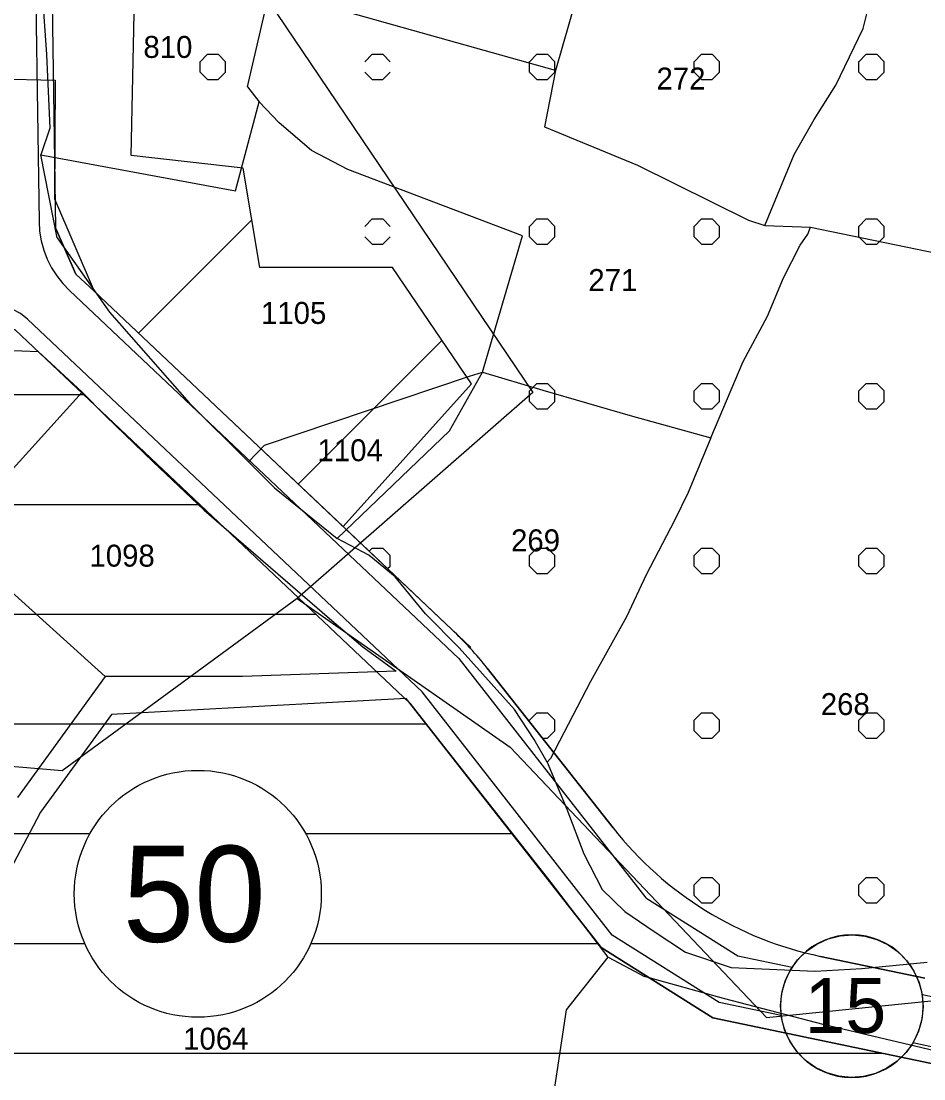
# Model space of a CAD drawing. Extents: x 410727 to 412947, y 4463506 to 4466382.
# Drawn here: x 411199.7 to 411364.1, y 4465992.7 to 4466185.4 of the extents above; entities that cross this region are included whole.
import ezdxf

# ---------------------------------------------------------------- set-up
doc = ezdxf.new("R2010")
doc.units = 0
for name, color, linetype in [('ADAKENARI', 7, 'Continuous'), ('KALDIRIM', 7, 'Continuous'), ('KDS_PARSEL_NO', 7, 'Continuous'), ('KDS_PL', 7, 'Continuous'), ('PL_KA_TARIM_OZEL', 7, 'Continuous'), ('PL_KON_ONE_50', 7, 'Continuous'), ('sembol', 7, 'Continuous'), ('SM_BEYAZ', 7, 'Continuous'), ('SM_DAİRE', 7, 'Continuous'), ('SM_YOLGEN', 7, 'Continuous'), ('SNR_KOYLER', 7, 'Continuous'), ('SNR_TR_AZGELISME', 7, 'Continuous'), ('TR_GELİŞME_KONUT_ÇOKAZ', 7, 'Continuous'), ('TR_OZELMAHSUL', 7, 'Continuous'), ('Yerlesime_uygunluk_sınırı', 7, 'Continuous')]:
    doc.layers.add(name, color=color, linetype=linetype)

msp = doc.modelspace()

# ---------------------------------------------------------------- linework, layer by layer
at = {"layer": 'ADAKENARI'}
for p, q in [((411205.32, 4466188.73), (411205.95, 4466147.79)), ((411209.66, 4466139.36), (411205.95, 4466147.79)), ((411212.98, 4466136.22), (411209.66, 4466139.36)), ((411258.32, 4466093.35), (411212.98, 4466136.22)), ((411281.62, 4466071.32), (411241.81, 4466108.96)), ((411278.17, 4466074.59), (411258.32, 4466093.35)), ((411307.51, 4466038.45), (411284.58, 4466067.56)), ((411364.32, 4466011.06), (411345.29, 4466015.03))]:
    msp.add_line(p, q, dxfattribs=at)
msp.add_lwpolyline([(411117.76, 4466023.84), (411156.49, 4466097.39), (411191.27, 4466129.24), (411198.59, 4466129.18), (411270.5, 4466061.2), (411305.33, 4466016.64), (411325.67, 4466003.81), (411366.7, 4465995.24)], dxfattribs=at)
for centre, start, end in [((411233.51, 4466027.35), 38.2144, 46.6065), ((411233.51, 4466027.35), 38.2144, 46.6065), ((411358.58, 4466078.66), 218.2144, 258.2027), ((411358.58, 4466078.66), 218.2144, 258.2027)]:
    msp.add_arc(centre, 65, start, end, dxfattribs=at)
at = {"layer": 'KALDIRIM'}
for points in [[(411198.93, 4466275.12), (411202.14, 4466255.53), (411208.26, 4466254.88), (411203.85, 4466225), (411202.32, 4466188.77), (411202.93, 4466148.93), (411203.04, 4466147.17), (411203.33, 4466145.44), (411203.79, 4466143.74), (411204.42, 4466142.09), (411205.21, 4466140.52), (411206.15, 4466139.03), (411207.24, 4466137.64), (411208.46, 4466136.37), (411279.4, 4466069.3), (411313.49, 4466025.68), (411330.24, 4466015.11), (411340.12, 4466013.05)], [(411338.13, 4466004.27), (411326.82, 4466006.63), (411307.37, 4466018.9), (411272.72, 4466063.22), (411200.86, 4466131.17), (411199.58, 4466132.17), (411198.14, 4466132.91), (411196.58, 4466133.37), (411194.96, 4466133.54), (411193.34, 4466133.4), (411191.78, 4466132.96), (411190.32, 4466132.24), (411189.03, 4466131.26), (411146.18, 4466092.01), (411131.2, 4466084.63), (411083.45, 4466076.24), (411040.64, 4466082.04), (411015.99, 4466078.54), (410988.76, 4466066.47)], [(411363.84, 4466008.09), (411368.56, 4466007.11), (411402.12, 4466003.58), (411420.29, 4465997.93), (411448.26, 4465982.75), (411504.51, 4465923.06), (411515.54, 4465913.29), (411544.92, 4465897.92), (411576.35, 4465881.49), (411596.27, 4465871.64)], [(411400.3, 4465994.72), (411367.17, 4465998.21), (411362.15, 4465999.25)]]:
    msp.add_lwpolyline(points, dxfattribs=at)
at = {"layer": 'KDS_PL'}
for p, q in [((411305.07, 4466204.22), (411297.02, 4466176.47)), ((411203.54, 4466190.27), (411204.27, 4466179.37)), ((411297.02, 4466176.47), (411245.89, 4466190.84)), ((411240.94, 4466173.48), (411244.24, 4466187.9)), ((411353.1, 4466184.12), (411353.76, 4466186.78)), ((411348.12, 4466173.81), (411353.1, 4466184.12)), ((411204.27, 4466179.37), (411204.89, 4466165.95)), ((411297.02, 4466176.47), (411295.03, 4466166.17)), ((411240.94, 4466173.48), (411243.06, 4466170.76)), ((411344.14, 4466167.5), (411348.12, 4466173.81)), ((411238.71, 4466154.52), (411243.06, 4466170.76)), ((411243.06, 4466170.76), (411246.67, 4466166.9)), ((411252.56, 4466161.9), (411246.67, 4466166.9)), ((411340.49, 4466161.18), (411344.14, 4466167.5)), ((411204.89, 4466165.95), (411203.24, 4466161.07)), ((411295.03, 4466166.17), (411311.95, 4466159.18)), ((411206.22, 4466145.96), (411203.24, 4466161.07)), ((411203.24, 4466161.07), (411238.71, 4466154.52)), ((411259.2, 4466158.4), (411252.56, 4466161.9)), ((411335.18, 4466148.21), (411340.49, 4466161.18)), ((411311.95, 4466159.18), (411332.19, 4466149.21)), ((411291.02, 4466146.31), (411259.2, 4466158.4)), ((411332.19, 4466149.21), (411335.18, 4466148.21)), ((411335.18, 4466148.21), (411343.47, 4466147.88)), ((411343.01, 4466146.61), (411343.47, 4466147.88)), ((411343.47, 4466147.88), (411377.65, 4466140.9)), ((411206.22, 4466145.96), (411215.76, 4466132.43)), ((411283.75, 4466121.51), (411291.02, 4466146.31)), ((411341.6, 4466144.62), (411343.01, 4466146.61)), ((411338.58, 4466138.68), (411341.6, 4466144.62)), ((411335.67, 4466131.7), (411338.58, 4466138.68)), ((411215.76, 4466132.43), (411230.3, 4466115.9)), ((411331.24, 4466123.4), (411335.67, 4466131.7)), ((411187.64, 4466125.92), (411202.76, 4466125.24)), ((411202.76, 4466125.24), (411210.76, 4466117.87)), ((411325.31, 4466109.54), (411331.24, 4466123.4)), ((411244.02, 4466108.17), (411281.35, 4466120.77)), ((411277.73, 4466110.77), (411283.75, 4466121.51)), ((411281.35, 4466120.77), (411283.75, 4466121.51)), ((411283.75, 4466121.51), (411294.72, 4466118.22)), ((411186.86, 4466091.42), (411210.76, 4466117.87)), ((411215.1, 4466113.49), (411210.76, 4466117.87)), ((411294.72, 4466118.22), (411310.63, 4466113.59)), ((411241.12, 4466105.12), (411230.3, 4466115.9)), ((411215.1, 4466113.49), (411223.7, 4466105.13)), ((411310.63, 4466113.59), (411325.31, 4466109.54)), ((411257.25, 4466091.18), (411277.73, 4466110.77)), ((411325.31, 4466109.54), (411321.17, 4466099.54)), ((411241.12, 4466105.12), (411244.02, 4466108.17)), ((411223.7, 4466105.13), (411233, 4466096.32)), ((411245.83, 4466100.43), (411241.12, 4466105.12)), ((411245.83, 4466100.43), (411257.25, 4466091.18)), ((411321.17, 4466099.54), (411318.72, 4466094.45)), ((411233, 4466096.32), (411255.88, 4466076.61)), ((411318.72, 4466094.45), (411313.54, 4466084.55)), ((411215, 4466066), (411186.86, 4466091.42)), ((411263, 4466088.13), (411257.25, 4466091.18)), ((411267.8, 4466084.17), (411263, 4466088.13)), ((411273.35, 4466077.47), (411267.8, 4466084.17)), ((411313.54, 4466084.55), (411309.97, 4466076.91)), ((411255.88, 4466076.61), (411261.93, 4466071.46)), ((411279.47, 4466071.25), (411273.35, 4466077.47)), ((411309.97, 4466076.91), (411303.38, 4466065.12)), ((411261.93, 4466071.46), (411268, 4466067)), ((411289.54, 4466060.03), (411279.47, 4466071.25)), ((411268, 4466067), (411240, 4466066)), ((411215, 4466066), (411199, 4466044)), ((411240, 4466066), (411215, 4466066)), ((411303.38, 4466065.12), (411296.13, 4466051.07)), ((411269.84, 4466062.04), (411216.13, 4466059.09)), ((411275.37, 4466055.02), (411269.84, 4466062.04)), ((411216.13, 4466059.09), (411203.2, 4466041.28)), ((411293.12, 4466054.55), (411289.54, 4466060.03)), ((411296.25, 4466028.5), (411275.37, 4466055.02)), ((411295.53, 4466050.43), (411293.12, 4466054.55)), ((411296.13, 4466051.07), (411295.53, 4466050.43)), ((411295.53, 4466050.43), (411299.07, 4466041.86)), ((411299.07, 4466041.86), (411302.2, 4466033.71)), ((411203.2, 4466041.28), (411201.87, 4466038.77)), ((411201.87, 4466038.77), (411183.37, 4466003.83)), ((411302.2, 4466033.71), (411305.54, 4466027.23)), ((411306.62, 4466014.89), (411296.25, 4466028.5)), ((411305.54, 4466027.23), (411309.69, 4466023.18)), ((411309.69, 4466023.18), (411315.01, 4466019.59)), ((411315.01, 4466019.59), (411320.72, 4466015.81)), ((411299.02, 4466005.3), (411306.62, 4466014.89)), ((411306.62, 4466014.89), (411313.26, 4466011.35)), ((411320.72, 4466015.81), (411329.04, 4466013)), ((411329.04, 4466013), (411344.31, 4466012.32)), ((411344.31, 4466012.32), (411352.82, 4466012.81)), ((411352.82, 4466012.81), (411364.72, 4466013.97)), ((411327.65, 4466007.38), (411313.26, 4466011.35)), ((411346.01, 4466002.57), (411327.65, 4466007.38)), ((411295.29, 4465980.46), (411299.02, 4466005.3)), ((411367.09, 4465997.59), (411346.01, 4466002.57))]:
    msp.add_line(p, q, dxfattribs=at)
at = {"layer": 'PL_KA_TARIM_OZEL'}
for points in [[(411205.32, 4466188.73), (411205.95, 4466147.79), (411209.66, 4466139.36), (411212.98, 4466136.22), (411241.81, 4466108.96), (411258.32, 4466093.35), (411278.17, 4466074.59)], [(411284.58, 4466067.56), (411307.51, 4466038.45)], [(411345.29, 4466015.03), (411364.32, 4466011.06)]]:
    msp.add_lwpolyline(points, dxfattribs=at)
for centre, start, end in [((411233.51, 4466027.35), 38.2144, 46.6065), ((411358.58, 4466078.66), 218.2144, 258.2027)]:
    msp.add_arc(centre, 65, start, end, dxfattribs=at)
at = {"layer": 'PL_KON_ONE_50'}
msp.add_lwpolyline([(411366.7, 4465995.24), (411325.67, 4466003.81), (411305.33, 4466016.64), (411270.5, 4466061.2), (411198.59, 4466129.18), (411191.27, 4466129.24), (411156.49, 4466097.39), (411117.76, 4466023.84), (411081.79, 4465955.55)], dxfattribs=at)
at = {"layer": 'sembol'}
msp.add_circle((411231.86, 4466026.43), 22.5, dxfattribs=at)
at = {"layer": 'SM_BEYAZ'}
for start, end in [(0, 180), (180, 0)]:
    msp.add_arc((411351.02, 4466005.96), 13, start, end, dxfattribs=at)
at = {"layer": 'SM_DAİRE'}
msp.add_lwpolyline([(411364.02, 4466005.83), (411363.8, 4466003.58), (411363.19, 4466001.39), (411362.21, 4465999.35), (411360.89, 4465997.51), (411359.28, 4465995.92), (411357.41, 4465994.64), (411355.34, 4465993.7), (411353.15, 4465993.14), (411350.89, 4465992.96), (411348.63, 4465993.18), (411346.45, 4465993.79), (411344.41, 4465994.77), (411342.56, 4465996.08), (411340.98, 4465997.7), (411339.7, 4465999.57), (411338.76, 4466001.63), (411338.19, 4466003.83), (411338.02, 4466006.09), (411338.24, 4466008.34), (411338.85, 4466010.53), (411339.82, 4466012.57), (411341.14, 4466014.41), (411342.76, 4466016), (411344.63, 4466017.28), (411346.69, 4466018.22), (411348.89, 4466018.79), (411351.15, 4466018.96), (411353.4, 4466018.74), (411355.58, 4466018.13), (411357.63, 4466017.15), (411359.47, 4466015.84), (411361.06, 4466014.22), (411362.34, 4466012.35), (411363.28, 4466010.29), (411363.84, 4466008.09), (411364.02, 4466005.83)], dxfattribs=at)
msp.add_lwpolyline([(411364.02, 4466005.83), (411363.8, 4466003.58), (411363.19, 4466001.39), (411362.21, 4465999.35), (411360.89, 4465997.51), (411359.28, 4465995.92), (411357.41, 4465994.64), (411355.34, 4465993.7), (411353.15, 4465993.14), (411350.89, 4465992.96), (411348.63, 4465993.18), (411346.45, 4465993.79), (411344.41, 4465994.77), (411342.56, 4465996.08), (411340.98, 4465997.7), (411339.7, 4465999.57), (411338.76, 4466001.63), (411338.19, 4466003.83), (411338.02, 4466006.09), (411338.24, 4466008.34), (411338.85, 4466010.53), (411339.82, 4466012.57), (411341.14, 4466014.41), (411342.76, 4466016), (411344.63, 4466017.28), (411346.69, 4466018.22), (411348.89, 4466018.79), (411351.15, 4466018.96), (411353.4, 4466018.74), (411355.58, 4466018.13), (411357.63, 4466017.15), (411359.47, 4466015.84), (411361.06, 4466014.22), (411362.34, 4466012.35), (411363.28, 4466010.29), (411363.84, 4466008.09), (411364.02, 4466005.83)], dxfattribs=at)
at = {"layer": 'SNR_KOYLER'}
for p, q in [((411219.73, 4466160.94), (411220.48, 4466197.23)), ((411190.9, 4466175), (411205.9, 4466174.7)), ((411205.9, 4466174.7), (411205.77, 4466153.09)), ((411240.14, 4466158.67), (411219.73, 4466160.94)), ((411243.17, 4466140.53), (411240.14, 4466158.67)), ((411205.77, 4466153.09), (411212.98, 4466136.22)), ((411267.36, 4466140.53), (411243.17, 4466140.53)), ((411281.73, 4466119.36), (411267.36, 4466140.53)), ((411212.98, 4466136.22), (411258.32, 4466093.35)), ((411258.32, 4466093.35), (411281.73, 4466119.36))]:
    msp.add_line(p, q, dxfattribs=at)
at = {"layer": 'SNR_TR_AZGELISME'}
for p, q in [((411221.06, 4466128.58), (411241.72, 4466149.23)), ((411250.14, 4466101.09), (411276.35, 4466127.29))]:
    msp.add_line(p, q, dxfattribs=at)
at = {"layer": 'TR_GELİŞME_KONUT_ÇOKAZ'}
for p, q in [((411178.33, 4466117.39), (411211.07, 4466117.39)), ((411156.49, 4466097.39), (411232.22, 4466097.39)), ((411145.96, 4466077.39), (411253.37, 4466077.39)), ((411135.43, 4466057.39), (411273.48, 4466057.39)), ((411124.89, 4466037.39), (411212.21, 4466037.39)), ((411251.51, 4466037.39), (411289.11, 4466037.39)), ((411114.36, 4466017.39), (411211.25, 4466017.39)), ((411252.46, 4466017.39), (411304.74, 4466017.39)), ((411103.83, 4465997.39), (411356.41, 4465997.39))]:
    msp.add_line(p, q, dxfattribs=at)
msp.add_lwpolyline([(411366.7, 4465995.24), (411325.67, 4466003.81), (411305.33, 4466016.64), (411270.5, 4466061.2), (411198.59, 4466129.18), (411191.27, 4466129.24)], dxfattribs=at)
at = {"layer": 'TR_OZELMAHSUL'}
for p, q in [((411232.29, 4466178.06), (411233.64, 4466179.42)), ((411233.64, 4466179.42), (411235.56, 4466179.42)), ((411236.92, 4466178.06), (411235.56, 4466179.41)), ((411262.29, 4466178.06), (411263.64, 4466179.42)), ((411263.64, 4466179.42), (411265.56, 4466179.42)), ((411266.92, 4466178.06), (411265.56, 4466179.41)), ((411292.28, 4466178.06), (411293.64, 4466179.42)), ((411293.64, 4466179.42), (411295.56, 4466179.42)), ((411296.92, 4466178.06), (411295.56, 4466179.41)), ((411322.28, 4466178.06), (411323.64, 4466179.42)), ((411323.64, 4466179.42), (411325.56, 4466179.42)), ((411326.92, 4466178.06), (411325.56, 4466179.41)), ((411352.28, 4466178.06), (411353.64, 4466179.42)), ((411353.64, 4466179.42), (411355.56, 4466179.42)), ((411356.92, 4466178.06), (411355.56, 4466179.41)), ((411232.29, 4466176.15), (411232.29, 4466178.07)), ((411236.91, 4466176.15), (411236.91, 4466178.07)), ((411292.29, 4466176.15), (411292.29, 4466178.07)), ((411296.91, 4466176.15), (411296.91, 4466178.07)), ((411322.29, 4466176.15), (411322.29, 4466178.07)), ((411326.91, 4466176.15), (411326.91, 4466178.07)), ((411352.29, 4466176.15), (411352.29, 4466178.07)), ((411356.91, 4466176.15), (411356.91, 4466178.07)), ((411233.65, 4466174.79), (411232.29, 4466176.14)), ((411233.64, 4466174.8), (411235.56, 4466174.8)), ((411235.56, 4466174.79), (411236.91, 4466176.15)), ((411263.65, 4466174.79), (411262.29, 4466176.14)), ((411263.64, 4466174.8), (411265.56, 4466174.8)), ((411265.56, 4466174.79), (411266.91, 4466176.15)), ((411293.65, 4466174.79), (411292.29, 4466176.14)), ((411293.64, 4466174.8), (411295.56, 4466174.8)), ((411295.55, 4466174.79), (411296.91, 4466176.15)), ((411323.65, 4466174.79), (411322.29, 4466176.14)), ((411323.64, 4466174.8), (411325.56, 4466174.8)), ((411325.55, 4466174.79), (411326.91, 4466176.15)), ((411353.65, 4466174.79), (411352.29, 4466176.14)), ((411353.64, 4466174.8), (411355.56, 4466174.8)), ((411355.55, 4466174.79), (411356.91, 4466176.15)), ((411262.29, 4466148.06), (411263.64, 4466149.42)), ((411263.64, 4466149.42), (411265.56, 4466149.42)), ((411266.92, 4466148.06), (411265.56, 4466149.41)), ((411292.28, 4466148.06), (411293.64, 4466149.42)), ((411292.29, 4466146.15), (411292.29, 4466148.07)), ((411293.64, 4466149.42), (411295.56, 4466149.42)), ((411296.92, 4466148.06), (411295.56, 4466149.41)), ((411296.91, 4466146.15), (411296.91, 4466148.07)), ((411322.28, 4466148.06), (411323.64, 4466149.42)), ((411322.29, 4466146.15), (411322.29, 4466148.07)), ((411323.64, 4466149.42), (411325.56, 4466149.42)), ((411326.92, 4466148.06), (411325.56, 4466149.41)), ((411326.91, 4466146.15), (411326.91, 4466148.07)), ((411352.28, 4466148.06), (411353.64, 4466149.42)), ((411352.29, 4466146.15), (411352.29, 4466148.07)), ((411353.64, 4466149.42), (411355.56, 4466149.42)), ((411356.92, 4466148.06), (411355.56, 4466149.41)), ((411356.91, 4466146.15), (411356.91, 4466148.07)), ((411263.65, 4466144.79), (411262.29, 4466146.14)), ((411265.56, 4466144.79), (411266.91, 4466146.15)), ((411293.65, 4466144.79), (411292.29, 4466146.14)), ((411295.55, 4466144.79), (411296.91, 4466146.15)), ((411323.65, 4466144.79), (411322.29, 4466146.14)), ((411325.55, 4466144.79), (411326.91, 4466146.15)), ((411353.65, 4466144.79), (411352.29, 4466146.14)), ((411355.55, 4466144.79), (411356.91, 4466146.15)), ((411263.64, 4466144.8), (411265.56, 4466144.8)), ((411293.64, 4466144.8), (411295.56, 4466144.8)), ((411323.64, 4466144.8), (411325.56, 4466144.8)), ((411353.64, 4466144.8), (411355.56, 4466144.8)), ((411292.28, 4466118.06), (411293.64, 4466119.42)), ((411293.64, 4466119.42), (411295.56, 4466119.42)), ((411296.92, 4466118.06), (411295.56, 4466119.42)), ((411322.28, 4466118.06), (411323.64, 4466119.42)), ((411323.64, 4466119.42), (411325.56, 4466119.42)), ((411326.92, 4466118.06), (411325.56, 4466119.42)), ((411352.28, 4466118.06), (411353.64, 4466119.42)), ((411353.64, 4466119.42), (411355.56, 4466119.42)), ((411356.92, 4466118.06), (411355.56, 4466119.42)), ((411292.29, 4466116.15), (411292.29, 4466118.07)), ((411296.91, 4466116.15), (411296.91, 4466118.07)), ((411322.29, 4466116.15), (411322.29, 4466118.07)), ((411326.91, 4466116.15), (411326.91, 4466118.07)), ((411352.29, 4466116.15), (411352.29, 4466118.07)), ((411356.91, 4466116.15), (411356.91, 4466118.07)), ((411293.65, 4466114.79), (411292.29, 4466116.15)), ((411293.64, 4466114.8), (411295.56, 4466114.8)), ((411295.55, 4466114.79), (411296.91, 4466116.15)), ((411323.65, 4466114.79), (411322.29, 4466116.15)), ((411323.64, 4466114.8), (411325.56, 4466114.8)), ((411325.55, 4466114.79), (411326.91, 4466116.15)), ((411353.65, 4466114.79), (411352.29, 4466116.15)), ((411353.64, 4466114.8), (411355.56, 4466114.8)), ((411355.55, 4466114.79), (411356.91, 4466116.15)), ((411263.08, 4466088.86), (411263.64, 4466089.42)), ((411263.64, 4466089.42), (411265.56, 4466089.42)), ((411266.92, 4466088.06), (411265.56, 4466089.42)), ((411266.91, 4466086.15), (411266.91, 4466088.07)), ((411292.28, 4466088.06), (411293.64, 4466089.42)), ((411292.29, 4466086.15), (411292.29, 4466088.07)), ((411293.64, 4466089.42), (411295.56, 4466089.42)), ((411296.92, 4466088.06), (411295.56, 4466089.42)), ((411296.91, 4466086.15), (411296.91, 4466088.07)), ((411322.28, 4466088.06), (411323.64, 4466089.42)), ((411322.29, 4466086.15), (411322.29, 4466088.07)), ((411323.64, 4466089.42), (411325.56, 4466089.42)), ((411326.92, 4466088.06), (411325.56, 4466089.42)), ((411326.91, 4466086.15), (411326.91, 4466088.07)), ((411352.28, 4466088.06), (411353.64, 4466089.42)), ((411352.29, 4466086.15), (411352.29, 4466088.07)), ((411353.64, 4466089.42), (411355.56, 4466089.42)), ((411356.91, 4466088.06), (411355.56, 4466089.42)), ((411356.91, 4466086.15), (411356.91, 4466088.07)), ((411266.44, 4466085.68), (411266.91, 4466086.15)), ((411293.65, 4466084.79), (411292.29, 4466086.15)), ((411295.55, 4466084.79), (411296.91, 4466086.15)), ((411323.65, 4466084.79), (411322.29, 4466086.15)), ((411325.55, 4466084.79), (411326.91, 4466086.15)), ((411353.64, 4466084.79), (411352.29, 4466086.15)), ((411355.55, 4466084.79), (411356.91, 4466086.15)), ((411293.64, 4466084.8), (411295.56, 4466084.8)), ((411323.64, 4466084.8), (411325.56, 4466084.8)), ((411353.64, 4466084.8), (411355.56, 4466084.8)), ((411292.28, 4466058.06), (411293.64, 4466059.42)), ((411293.64, 4466059.42), (411295.56, 4466059.42)), ((411296.91, 4466058.06), (411295.56, 4466059.42)), ((411322.28, 4466058.06), (411323.64, 4466059.42)), ((411323.64, 4466059.42), (411325.56, 4466059.42)), ((411326.91, 4466058.06), (411325.56, 4466059.42)), ((411352.28, 4466058.06), (411353.64, 4466059.42)), ((411353.64, 4466059.42), (411355.56, 4466059.42)), ((411356.91, 4466058.06), (411355.56, 4466059.42)), ((411292.29, 4466057.78), (411292.29, 4466058.07)), ((411296.91, 4466056.15), (411296.91, 4466058.07)), ((411322.29, 4466056.15), (411322.29, 4466058.07)), ((411326.91, 4466056.15), (411326.91, 4466058.07)), ((411352.29, 4466056.15), (411352.29, 4466058.07)), ((411356.91, 4466056.15), (411356.91, 4466058.07)), ((411295.55, 4466054.79), (411296.91, 4466056.15)), ((411323.64, 4466054.79), (411322.29, 4466056.15)), ((411325.55, 4466054.79), (411326.91, 4466056.15)), ((411353.64, 4466054.79), (411352.29, 4466056.15)), ((411355.55, 4466054.79), (411356.91, 4466056.15)), ((411294.64, 4466054.8), (411295.56, 4466054.8)), ((411323.64, 4466054.8), (411325.56, 4466054.8)), ((411353.64, 4466054.8), (411355.56, 4466054.8)), ((411322.28, 4466028.06), (411323.64, 4466029.42)), ((411322.29, 4466026.15), (411322.29, 4466028.07)), ((411323.64, 4466029.42), (411325.56, 4466029.42)), ((411326.91, 4466028.06), (411325.56, 4466029.42)), ((411326.91, 4466026.15), (411326.91, 4466028.07)), ((411352.28, 4466028.06), (411353.64, 4466029.42)), ((411352.29, 4466026.15), (411352.29, 4466028.07)), ((411353.64, 4466029.42), (411355.56, 4466029.42)), ((411356.91, 4466028.06), (411355.56, 4466029.42)), ((411356.91, 4466026.15), (411356.91, 4466028.07)), ((411323.64, 4466024.79), (411322.29, 4466026.15)), ((411325.55, 4466024.79), (411326.91, 4466026.15)), ((411353.64, 4466024.79), (411352.29, 4466026.15)), ((411355.55, 4466024.79), (411356.91, 4466026.15)), ((411323.64, 4466024.8), (411325.56, 4466024.8)), ((411353.64, 4466024.8), (411355.56, 4466024.8))]:
    msp.add_line(p, q, dxfattribs=at)
at = {"layer": 'Yerlesime_uygunluk_sınırı'}
for points in [[(411367.59, 4466324.54), (411367.57, 4466324.45), (411365.4, 4466317.37), (411329.85, 4466256.4), (411327.98, 4466256.94), (411298.02, 4466265.64), (411235.39, 4466203.01), (411292.89, 4466117.8), (411249.96, 4466080.27), (411288.76, 4466053.15), (411335.49, 4466003.87), (411401.49, 4466010.55), (411454, 4465988), (411518.19, 4465927.25), (411576.49, 4465880.17), (411546.8, 4465853.02), (411462.76, 4465826.95), (411417.87, 4465818.6), (411360.95, 4465816.44), (411257.66, 4465822.32), (411198.74, 4465810.19), (411081.53, 4465694.24)], [(411249.96, 4466080.27), (411207.16, 4466048.84), (411087.92, 4466058.92), (411061.58, 4466077.97), (411022.9, 4466078.53), (410939.01, 4466044.04), (410793.61, 4466010.63)]]:
    msp.add_lwpolyline(points, dxfattribs=at)

# ---------------------------------------------------------------- texts
at = {"layer": 'KDS_PARSEL_NO'}
for s, p in [('810', (411221.95, 4466178.75)), ('272', (411315.43, 4466172.99)), ('271', (411303.01, 4466136.27)), ('1105', (411243.37, 4466130.28)), ('1104', (411253.67, 4466105.26)), ('269', (411288.93, 4466088.84)), ('1098', (411212.12, 4466086.05)), ('268', (411345.36, 4466059)), ('1064', (411229.18, 4465998.03))]:
    msp.add_text(s, height=4, dxfattribs=at).set_placement(p)
at = {"layer": 'sembol'}
msp.add_text('50', height=17.5, dxfattribs=at).set_placement((411218.19, 4466017.68))
at = {"layer": 'SM_YOLGEN'}
msp.add_text('15', height=10, dxfattribs=at).set_placement((411342.41, 4466001.06))
msp.add_text('15', height=10, dxfattribs=at).set_placement((411342.41, 4466001.06))

doc.saveas('drawing.dxf')
